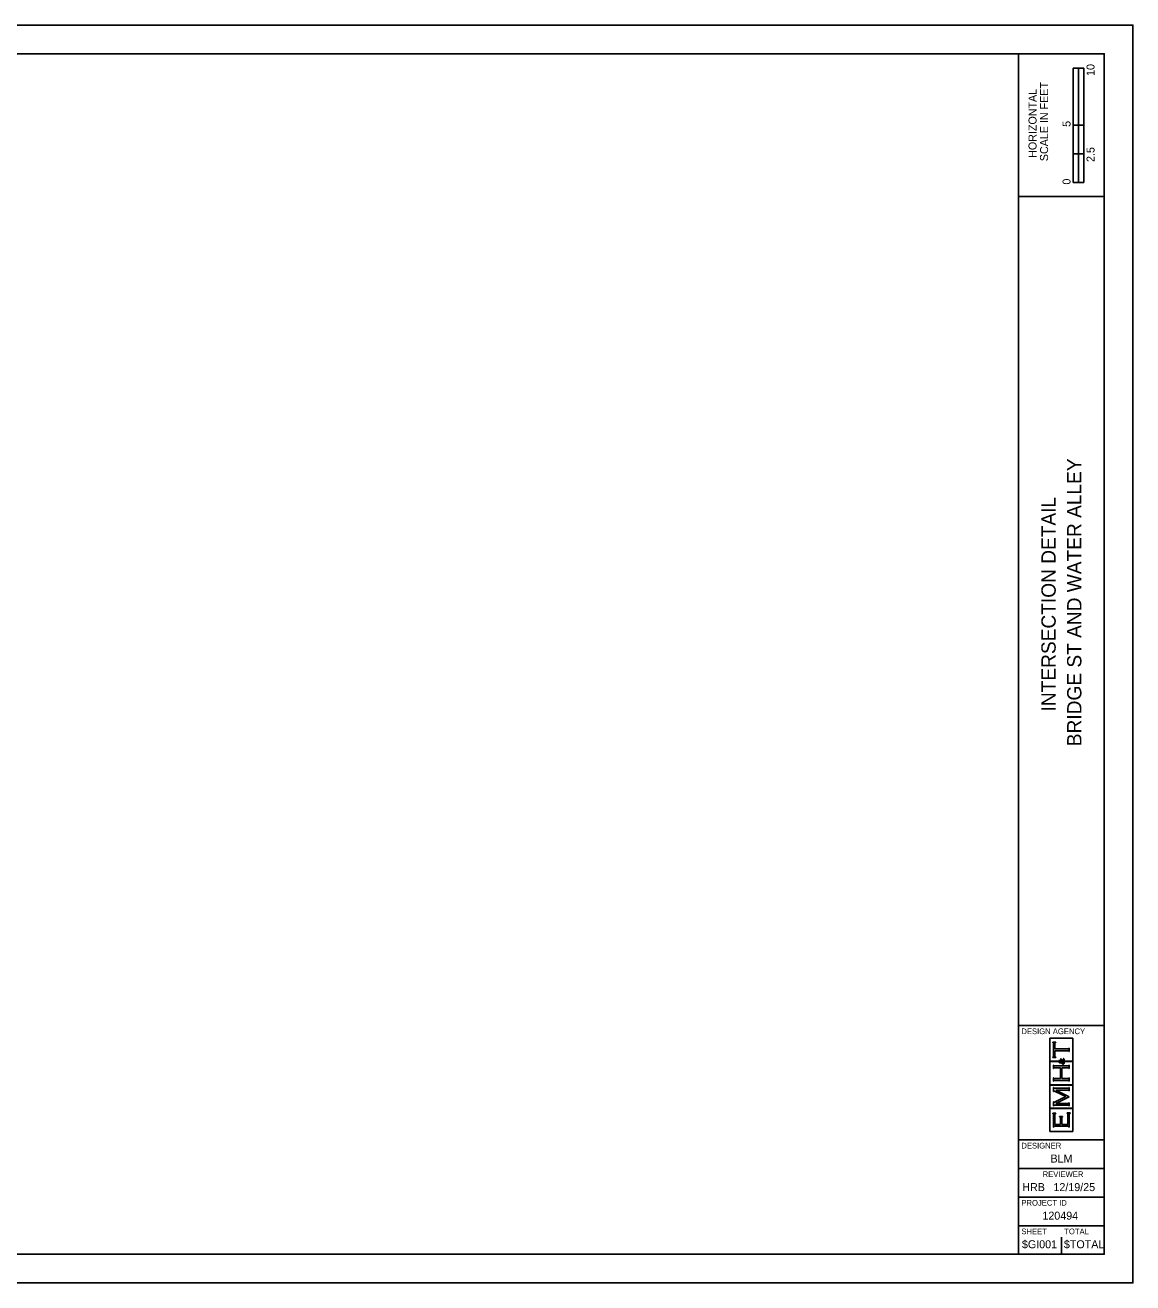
# Model space of a CAD drawing. Extents: x -4.8 to 34, y 0 to 22.
# Drawn here: x 14.62 to 34, y 0 to 22 of the extents above; entities that cross this region are included whole.
import ezdxf

# ---------------------------------------------------------------- set-up
doc = ezdxf.new("R2010")
doc.units = 0
for name, color, linetype in [('CM_Corridor_Conceptual', 7, 'Continuous'), ('CM_Corridor_Range_Conceptual', 7, 'Continuous'), ('MD_P_ACB_B', 7, 'Continuous')]:
    doc.layers.add(name, color=color, linetype=linetype)

msp = doc.modelspace()

# ---------------------------------------------------------------- linework, layer by layer
at = {"layer": 'CM_Corridor_Conceptual'}
msp.add_lwpolyline([(0, 0), (34, 0), (34, 22), (0, 22)], close=True, dxfattribs=at)
at = {"layer": 'CM_Corridor_Range_Conceptual'}
for p, q in [((32, 0.5), (32, 21.5)), ((32, 19), (33.5, 19)), ((32, 4.5), (33.5, 4.5)), ((32, 2.5), (33.5, 2.5)), ((32, 2), (33.5, 2)), ((32, 1.5), (33.5, 1.5)), ((32, 1), (33.5, 1))]:
    msp.add_line(p, q, dxfattribs=at)
msp.add_lwpolyline([(1.5, 21.5), (33.5, 21.5), (33.5, 0.5), (1.5, 0.5)], close=True, dxfattribs=at)
at = {"layer": 'MD_P_ACB_B'}
for p, q in [((32.957, 19.25), (32.957, 21.25)), ((33.144, 21.25), (32.957, 21.25)), ((32.957, 20.25), (32.957, 21.25)), ((32.957, 21.25), (33.05, 21.25)), ((33.05, 21.25), (33.051, 21.25)), ((33.051, 21.25), (33.051, 20.25)), ((33.144, 21.25), (33.144, 19.25)), ((33.051, 20.25), (32.957, 20.25)), ((33.143, 20.25), (33.05, 20.25)), ((33.05, 20.25), (33.05, 19.75)), ((33.143, 19.75), (33.143, 20.25)), ((33.05, 19.75), (32.957, 19.75)), ((32.957, 19.75), (32.957, 19.25)), ((33.05, 19.25), (33.05, 19.75)), ((33.05, 19.75), (33.143, 19.75)), ((33.144, 19.25), (32.957, 19.25)), ((32.957, 19.25), (33.05, 19.25)), ((32.952, 4.279), (32.547, 4.279)), ((32.547, 4.279), (32.547, 3.875)), ((32.598, 4.204), (32.598, 4.211)), ((32.598, 4.211), (32.65, 4.211)), ((32.603, 4.203), (32.598, 4.204)), ((32.606, 4.201), (32.603, 4.203)), ((32.608, 4.199), (32.606, 4.201)), ((32.61, 4.196), (32.608, 4.199)), ((32.611, 4.192), (32.61, 4.196)), ((32.611, 4.187), (32.611, 4.192)), ((32.611, 3.968), (32.611, 4.187)), ((32.638, 4.196), (32.637, 4.192)), ((32.637, 4.192), (32.637, 4.187)), ((32.637, 4.187), (32.637, 4.093)), ((32.64, 4.199), (32.638, 4.196)), ((32.642, 4.201), (32.64, 4.199)), ((32.645, 4.203), (32.642, 4.201)), ((32.65, 4.204), (32.645, 4.203)), ((32.65, 4.211), (32.65, 4.204)), ((32.952, 3.875), (32.952, 4.279)), ((32.61, 3.958), (32.611, 3.962)), ((32.611, 3.962), (32.611, 3.968)), ((32.637, 4.093), (32.864, 4.093)), ((32.864, 4.061), (32.637, 4.061)), ((32.637, 4.061), (32.637, 3.968)), ((32.637, 3.968), (32.637, 3.962)), ((32.637, 3.962), (32.638, 3.958)), ((32.864, 4.093), (32.869, 4.093)), ((32.87, 4.061), (32.864, 4.061)), ((32.869, 4.093), (32.873, 4.094)), ((32.874, 4.06), (32.87, 4.061)), ((32.873, 4.094), (32.876, 4.096)), ((32.876, 4.059), (32.874, 4.06)), ((32.876, 4.096), (32.878, 4.097)), ((32.878, 4.057), (32.876, 4.059)), ((32.878, 4.097), (32.88, 4.101)), ((32.88, 4.053), (32.878, 4.057)), ((32.88, 4.101), (32.881, 4.106)), ((32.881, 4.048), (32.88, 4.053)), ((32.881, 4.106), (32.888, 4.106)), ((32.888, 4.048), (32.881, 4.048)), ((32.888, 4.106), (32.888, 4.048)), ((32.547, 3.875), (32.696, 3.875)), ((32.696, 3.869), (32.547, 3.869)), ((32.547, 3.869), (32.547, 3.465)), ((32.598, 3.95), (32.603, 3.951)), ((32.598, 3.944), (32.598, 3.95)), ((32.65, 3.944), (32.598, 3.944)), ((32.603, 3.951), (32.606, 3.953)), ((32.606, 3.953), (32.608, 3.955)), ((32.608, 3.955), (32.61, 3.958)), ((32.611, 3.749), (32.611, 3.807)), ((32.611, 3.807), (32.617, 3.807)), ((32.617, 3.749), (32.611, 3.749)), ((32.617, 3.807), (32.619, 3.802)), ((32.618, 3.754), (32.617, 3.749)), ((32.62, 3.758), (32.618, 3.754)), ((32.619, 3.802), (32.62, 3.798)), ((32.62, 3.798), (32.623, 3.797)), ((32.623, 3.76), (32.62, 3.758)), ((32.623, 3.797), (32.625, 3.795)), ((32.625, 3.761), (32.623, 3.76)), ((32.625, 3.795), (32.629, 3.794)), ((32.629, 3.762), (32.625, 3.761)), ((32.629, 3.794), (32.635, 3.794)), ((32.635, 3.762), (32.629, 3.762)), ((32.635, 3.794), (32.864, 3.794)), ((32.732, 3.762), (32.635, 3.762)), ((32.638, 3.958), (32.64, 3.955)), ((32.64, 3.955), (32.642, 3.953)), ((32.642, 3.953), (32.645, 3.951)), ((32.645, 3.951), (32.65, 3.95)), ((32.65, 3.95), (32.65, 3.944)), ((32.696, 3.875), (32.696, 3.869)), ((32.703, 3.879), (32.705, 3.883)), ((32.703, 3.873), (32.703, 3.879)), ((32.703, 3.868), (32.703, 3.873)), ((32.705, 3.863), (32.703, 3.868)), ((32.705, 3.883), (32.708, 3.887)), ((32.708, 3.858), (32.705, 3.863)), ((32.708, 3.887), (32.711, 3.89)), ((32.709, 3.879), (32.708, 3.876)), ((32.708, 3.876), (32.708, 3.873)), ((32.708, 3.873), (32.708, 3.869)), ((32.708, 3.869), (32.71, 3.866)), ((32.712, 3.853), (32.708, 3.858)), ((32.712, 3.881), (32.709, 3.879)), ((32.71, 3.866), (32.712, 3.864)), ((32.711, 3.89), (32.715, 3.892)), ((32.714, 3.883), (32.712, 3.881)), ((32.712, 3.864), (32.715, 3.862)), ((32.718, 3.85), (32.712, 3.853)), ((32.716, 3.884), (32.714, 3.883)), ((32.715, 3.892), (32.72, 3.892)), ((32.715, 3.862), (32.718, 3.861)), ((32.72, 3.884), (32.716, 3.884)), ((32.718, 3.861), (32.721, 3.861)), ((32.726, 3.85), (32.718, 3.85)), ((32.72, 3.892), (32.725, 3.892)), ((32.724, 3.884), (32.72, 3.884)), ((32.721, 3.861), (32.723, 3.861)), ((32.723, 3.861), (32.725, 3.862)), ((32.728, 3.882), (32.724, 3.884)), ((32.725, 3.892), (32.729, 3.89)), ((32.725, 3.862), (32.728, 3.862)), ((32.729, 3.85), (32.726, 3.85)), ((32.731, 3.88), (32.728, 3.882)), ((32.728, 3.862), (32.731, 3.863)), ((32.729, 3.89), (32.732, 3.887)), ((32.731, 3.85), (32.729, 3.85)), ((32.734, 3.877), (32.731, 3.88)), ((32.731, 3.863), (32.735, 3.865)), ((32.734, 3.851), (32.731, 3.85)), ((32.732, 3.887), (32.736, 3.883)), ((32.732, 3.572), (32.732, 3.762)), ((32.737, 3.872), (32.734, 3.877)), ((32.737, 3.852), (32.734, 3.851)), ((32.735, 3.865), (32.74, 3.867)), ((32.736, 3.883), (32.74, 3.878)), ((32.74, 3.867), (32.737, 3.872)), ((32.741, 3.853), (32.737, 3.852)), ((32.738, 3.893), (32.738, 3.922)), ((32.738, 3.922), (32.741, 3.922)), ((32.741, 3.893), (32.738, 3.893)), ((32.74, 3.878), (32.744, 3.869)), ((32.741, 3.922), (32.741, 3.918)), ((32.741, 3.918), (32.742, 3.915)), ((32.742, 3.896), (32.741, 3.895)), ((32.741, 3.895), (32.741, 3.893)), ((32.746, 3.855), (32.741, 3.853)), ((32.742, 3.915), (32.743, 3.913)), ((32.743, 3.897), (32.742, 3.896)), ((32.743, 3.913), (32.745, 3.911)), ((32.745, 3.899), (32.743, 3.897)), ((32.744, 3.869), (32.754, 3.875)), ((32.745, 3.911), (32.749, 3.908)), ((32.746, 3.899), (32.745, 3.899)), ((32.748, 3.899), (32.746, 3.899)), ((32.752, 3.844), (32.746, 3.855)), ((32.755, 3.899), (32.748, 3.899)), ((32.749, 3.908), (32.756, 3.904)), ((32.756, 3.86), (32.751, 3.857)), ((32.751, 3.857), (32.754, 3.852)), ((32.757, 3.837), (32.752, 3.844)), ((32.754, 3.875), (32.764, 3.881)), ((32.754, 3.852), (32.757, 3.848)), ((32.763, 3.895), (32.755, 3.899)), ((32.756, 3.904), (32.763, 3.9)), ((32.761, 3.863), (32.756, 3.86)), ((32.757, 3.848), (32.761, 3.845)), ((32.763, 3.833), (32.757, 3.837)), ((32.864, 3.762), (32.759, 3.762)), ((32.759, 3.762), (32.759, 3.572)), ((32.764, 3.865), (32.761, 3.863)), ((32.761, 3.845), (32.765, 3.843)), ((32.763, 3.9), (32.77, 3.896)), ((32.772, 3.887), (32.763, 3.895)), ((32.768, 3.829), (32.763, 3.833)), ((32.764, 3.881), (32.772, 3.887)), ((32.768, 3.867), (32.764, 3.865)), ((32.765, 3.843), (32.769, 3.841)), ((32.774, 3.872), (32.768, 3.867)), ((32.774, 3.827), (32.768, 3.829)), ((32.769, 3.841), (32.773, 3.841)), ((32.77, 3.896), (32.776, 3.891)), ((32.773, 3.841), (32.778, 3.841)), ((32.782, 3.878), (32.774, 3.872)), ((32.779, 3.827), (32.774, 3.827)), ((32.776, 3.891), (32.781, 3.895)), ((32.778, 3.841), (32.782, 3.843)), ((32.779, 3.923), (32.781, 3.926)), ((32.782, 3.922), (32.779, 3.923)), ((32.785, 3.827), (32.779, 3.827)), ((32.781, 3.926), (32.787, 3.924)), ((32.781, 3.895), (32.784, 3.898)), ((32.785, 3.921), (32.782, 3.922)), ((32.786, 3.873), (32.782, 3.878)), ((32.782, 3.843), (32.786, 3.846)), ((32.784, 3.898), (32.786, 3.901)), ((32.786, 3.919), (32.785, 3.921)), ((32.79, 3.829), (32.785, 3.827)), ((32.788, 3.917), (32.786, 3.919)), ((32.786, 3.901), (32.788, 3.904)), ((32.791, 3.886), (32.786, 3.881)), ((32.786, 3.881), (32.791, 3.876)), ((32.788, 3.869), (32.786, 3.873)), ((32.786, 3.846), (32.789, 3.849)), ((32.787, 3.924), (32.792, 3.921)), ((32.789, 3.914), (32.788, 3.917)), ((32.788, 3.904), (32.789, 3.908)), ((32.79, 3.867), (32.788, 3.869)), ((32.789, 3.911), (32.789, 3.914)), ((32.789, 3.908), (32.789, 3.911)), ((32.789, 3.849), (32.791, 3.853)), ((32.791, 3.864), (32.79, 3.867)), ((32.793, 3.834), (32.79, 3.829)), ((32.794, 3.89), (32.791, 3.886)), ((32.791, 3.876), (32.795, 3.87)), ((32.791, 3.861), (32.791, 3.864)), ((32.791, 3.859), (32.791, 3.861)), ((32.791, 3.853), (32.791, 3.859)), ((32.792, 3.921), (32.795, 3.918)), ((32.797, 3.838), (32.793, 3.834)), ((32.796, 3.894), (32.794, 3.89)), ((32.795, 3.918), (32.798, 3.914)), ((32.795, 3.87), (32.797, 3.866)), ((32.798, 3.897), (32.796, 3.894)), ((32.797, 3.866), (32.798, 3.861)), ((32.799, 3.844), (32.797, 3.838)), ((32.798, 3.914), (32.799, 3.91)), ((32.799, 3.901), (32.798, 3.897)), ((32.798, 3.861), (32.799, 3.857)), ((32.799, 3.91), (32.799, 3.905)), ((32.799, 3.905), (32.799, 3.901)), ((32.803, 3.869), (32.799, 3.875)), ((32.799, 3.875), (32.952, 3.875)), ((32.799, 3.857), (32.799, 3.852)), ((32.799, 3.852), (32.799, 3.844)), ((32.952, 3.869), (32.803, 3.869)), ((32.864, 3.794), (32.869, 3.794)), ((32.87, 3.762), (32.864, 3.762)), ((32.869, 3.794), (32.873, 3.795)), ((32.874, 3.761), (32.87, 3.762)), ((32.873, 3.795), (32.876, 3.797)), ((32.876, 3.76), (32.874, 3.761)), ((32.876, 3.797), (32.878, 3.798)), ((32.878, 3.758), (32.876, 3.76)), ((32.878, 3.798), (32.88, 3.802)), ((32.88, 3.754), (32.878, 3.758)), ((32.88, 3.802), (32.881, 3.807)), ((32.881, 3.749), (32.88, 3.754)), ((32.881, 3.807), (32.888, 3.807)), ((32.888, 3.749), (32.881, 3.749)), ((32.888, 3.807), (32.888, 3.749)), ((32.952, 3.465), (32.952, 3.869)), ((32.611, 3.527), (32.611, 3.585)), ((32.611, 3.585), (32.617, 3.585)), ((32.617, 3.527), (32.611, 3.527)), ((32.617, 3.585), (32.619, 3.58)), ((32.618, 3.532), (32.617, 3.527)), ((32.62, 3.536), (32.618, 3.532)), ((32.619, 3.58), (32.62, 3.576)), ((32.62, 3.576), (32.623, 3.574)), ((32.623, 3.537), (32.62, 3.536)), ((32.623, 3.574), (32.625, 3.573)), ((32.625, 3.539), (32.623, 3.537)), ((32.625, 3.573), (32.629, 3.572)), ((32.629, 3.54), (32.625, 3.539)), ((32.629, 3.572), (32.635, 3.572)), ((32.635, 3.54), (32.629, 3.54)), ((32.635, 3.572), (32.732, 3.572)), ((32.864, 3.54), (32.635, 3.54)), ((32.759, 3.572), (32.864, 3.572)), ((32.864, 3.572), (32.87, 3.572)), ((32.87, 3.54), (32.864, 3.54)), ((32.87, 3.572), (32.874, 3.573)), ((32.874, 3.539), (32.87, 3.54)), ((32.874, 3.573), (32.876, 3.574)), ((32.876, 3.538), (32.874, 3.539)), ((32.876, 3.574), (32.878, 3.576)), ((32.878, 3.536), (32.876, 3.538)), ((32.878, 3.576), (32.88, 3.58)), ((32.88, 3.532), (32.878, 3.536)), ((32.88, 3.58), (32.881, 3.585)), ((32.881, 3.527), (32.88, 3.532)), ((32.881, 3.585), (32.888, 3.585)), ((32.888, 3.527), (32.881, 3.527)), ((32.888, 3.585), (32.888, 3.527)), ((32.547, 3.465), (32.952, 3.465)), ((32.952, 3.459), (32.547, 3.459)), ((32.547, 3.459), (32.547, 3.055)), ((32.611, 3.345), (32.611, 3.418)), ((32.611, 3.418), (32.617, 3.418)), ((32.617, 3.345), (32.611, 3.345)), ((32.617, 3.418), (32.619, 3.412)), ((32.62, 3.352), (32.617, 3.345)), ((32.619, 3.412), (32.62, 3.409)), ((32.62, 3.409), (32.623, 3.407)), ((32.622, 3.355), (32.62, 3.352)), ((32.626, 3.355), (32.622, 3.355)), ((32.623, 3.407), (32.625, 3.405)), ((32.625, 3.405), (32.629, 3.405)), ((32.629, 3.355), (32.626, 3.355)), ((32.629, 3.405), (32.635, 3.405)), ((32.633, 3.353), (32.629, 3.355)), ((32.64, 3.35), (32.633, 3.353)), ((32.635, 3.405), (32.864, 3.405)), ((32.825, 3.257), (32.64, 3.35)), ((32.864, 3.373), (32.654, 3.373)), ((32.654, 3.373), (32.888, 3.255)), ((32.75, 3.5), (32.75, 3.5)), ((32.864, 3.405), (32.869, 3.405)), ((32.87, 3.373), (32.864, 3.373)), ((32.869, 3.405), (32.873, 3.405)), ((32.874, 3.372), (32.87, 3.373)), ((32.873, 3.405), (32.876, 3.407)), ((32.876, 3.37), (32.874, 3.372)), ((32.876, 3.407), (32.878, 3.409)), ((32.878, 3.369), (32.876, 3.37)), ((32.878, 3.409), (32.88, 3.412)), ((32.88, 3.365), (32.878, 3.369)), ((32.88, 3.412), (32.881, 3.418)), ((32.881, 3.36), (32.88, 3.365)), ((32.881, 3.418), (32.888, 3.418)), ((32.888, 3.36), (32.881, 3.36)), ((32.888, 3.418), (32.888, 3.36)), ((32.952, 3.055), (32.952, 3.459)), ((32.611, 3.096), (32.611, 3.168)), ((32.611, 3.168), (32.617, 3.168)), ((32.617, 3.096), (32.611, 3.096)), ((32.617, 3.168), (32.62, 3.162)), ((32.618, 3.102), (32.617, 3.096)), ((32.62, 3.105), (32.618, 3.102)), ((32.62, 3.162), (32.622, 3.158)), ((32.623, 3.107), (32.62, 3.105)), ((32.622, 3.158), (32.626, 3.158)), ((32.625, 3.109), (32.623, 3.107)), ((32.629, 3.109), (32.625, 3.109)), ((32.626, 3.158), (32.627, 3.158)), ((32.627, 3.158), (32.633, 3.161)), ((32.635, 3.109), (32.629, 3.109)), ((32.633, 3.161), (32.641, 3.165)), ((32.864, 3.109), (32.635, 3.109)), ((32.641, 3.165), (32.825, 3.257)), ((32.888, 3.255), (32.654, 3.138)), ((32.654, 3.138), (32.864, 3.138)), ((32.864, 3.138), (32.869, 3.138)), ((32.87, 3.109), (32.864, 3.109)), ((32.869, 3.138), (32.873, 3.139)), ((32.874, 3.109), (32.87, 3.109)), ((32.873, 3.139), (32.876, 3.141)), ((32.876, 3.107), (32.874, 3.109)), ((32.876, 3.141), (32.878, 3.143)), ((32.878, 3.105), (32.876, 3.107)), ((32.878, 3.143), (32.88, 3.146)), ((32.88, 3.102), (32.878, 3.105)), ((32.88, 3.146), (32.881, 3.151)), ((32.881, 3.096), (32.88, 3.102)), ((32.881, 3.151), (32.888, 3.151)), ((32.888, 3.096), (32.881, 3.096)), ((32.888, 3.151), (32.888, 3.096)), ((32.547, 3.055), (32.952, 3.055)), ((32.952, 3.049), (32.547, 3.049)), ((32.547, 3.049), (32.547, 2.645)), ((32.598, 2.962), (32.598, 2.969)), ((32.598, 2.969), (32.65, 2.969)), ((32.603, 2.961), (32.598, 2.962)), ((32.606, 2.959), (32.603, 2.961)), ((32.608, 2.957), (32.606, 2.959)), ((32.61, 2.955), (32.608, 2.957)), ((32.611, 2.951), (32.61, 2.955)), ((32.611, 2.945), (32.611, 2.951)), ((32.611, 2.725), (32.611, 2.945)), ((32.64, 2.957), (32.638, 2.955)), ((32.638, 2.955), (32.638, 2.951)), ((32.638, 2.951), (32.638, 2.945)), ((32.638, 2.945), (32.638, 2.77)), ((32.642, 2.959), (32.64, 2.957)), ((32.645, 2.961), (32.642, 2.959)), ((32.65, 2.962), (32.645, 2.961)), ((32.65, 2.969), (32.65, 2.962)), ((32.719, 2.902), (32.719, 2.908)), ((32.719, 2.908), (32.772, 2.908)), ((32.724, 2.901), (32.719, 2.902)), ((32.728, 2.899), (32.724, 2.901)), ((32.729, 2.896), (32.728, 2.899)), ((32.731, 2.894), (32.729, 2.896)), ((32.732, 2.89), (32.731, 2.894)), ((32.732, 2.884), (32.732, 2.89)), ((32.732, 2.77), (32.732, 2.884)), ((32.76, 2.894), (32.759, 2.89)), ((32.759, 2.89), (32.759, 2.884)), ((32.759, 2.884), (32.759, 2.77)), ((32.761, 2.896), (32.76, 2.894)), ((32.763, 2.899), (32.761, 2.896)), ((32.767, 2.901), (32.763, 2.899)), ((32.772, 2.902), (32.767, 2.901)), ((32.772, 2.908), (32.772, 2.902)), ((32.848, 2.965), (32.848, 2.972)), ((32.848, 2.972), (32.901, 2.972)), ((32.853, 2.964), (32.848, 2.965)), ((32.857, 2.962), (32.853, 2.964)), ((32.859, 2.96), (32.857, 2.962)), ((32.86, 2.958), (32.859, 2.96)), ((32.861, 2.953), (32.86, 2.958)), ((32.861, 2.948), (32.861, 2.953)), ((32.861, 2.77), (32.861, 2.948)), ((32.889, 2.957), (32.888, 2.953)), ((32.888, 2.953), (32.888, 2.948)), ((32.888, 2.948), (32.888, 2.725)), ((32.891, 2.96), (32.889, 2.957)), ((32.892, 2.962), (32.891, 2.96)), ((32.896, 2.964), (32.892, 2.962)), ((32.901, 2.965), (32.896, 2.964)), ((32.901, 2.972), (32.901, 2.965)), ((32.952, 2.645), (32.952, 3.049)), ((32.547, 2.645), (32.952, 2.645)), ((32.617, 2.725), (32.611, 2.725)), ((32.619, 2.73), (32.617, 2.725)), ((32.62, 2.734), (32.619, 2.73)), ((32.623, 2.735), (32.62, 2.734)), ((32.625, 2.737), (32.623, 2.735)), ((32.629, 2.738), (32.625, 2.737)), ((32.635, 2.738), (32.629, 2.738)), ((32.864, 2.738), (32.635, 2.738)), ((32.638, 2.77), (32.732, 2.77)), ((32.759, 2.77), (32.861, 2.77)), ((32.87, 2.738), (32.864, 2.738)), ((32.874, 2.737), (32.87, 2.738)), ((32.876, 2.735), (32.874, 2.737)), ((32.878, 2.734), (32.876, 2.735)), ((32.88, 2.73), (32.878, 2.734)), ((32.881, 2.725), (32.88, 2.73)), ((32.888, 2.725), (32.881, 2.725)), ((32.375, 0.675), (32.375, 0.675)), ((32.75, 0.5), (32.75, 0.8))]:
    msp.add_line(p, q, dxfattribs=at)

# ---------------------------------------------------------------- texts
for s, height, p in [('10', 0.14, (33.33, 21.112)), ('SCALE IN FEET', 0.14, (32.517, 19.621)), ('HORIZONTAL', 0.14, (32.315, 19.679)), ('5', 0.14, (32.91, 20.221)), ('2.5', 0.14, (33.33, 19.607)), ('0', 0.14, (32.91, 19.211)), ('BRIDGE ST AND WATER ALLEY', 0.25, (33.1, 9.387)), ('INTERSECTION DETAIL', 0.25, (32.65, 9.996))]:
    msp.add_text(s, height=height, rotation=90, dxfattribs=at).set_placement(p)
for s, height, p in [('DESIGN AGENCY', 0.1, (32.05, 4.35)), ('DESIGNER', 0.1, (32.05, 2.35)), ('BLM', 0.14, (32.559, 2.105)), ('REVIEWER', 0.1, (32.422, 1.85)), ('HRB', 0.14, (32.066, 1.605)), ('12/19/25', 0.14, (32.611, 1.605)), ('PROJECT ID', 0.1, (32.05, 1.35)), ('120494', 0.14, (32.418, 1.105)), ('SHEET', 0.1, (32.05, 0.85)), ('TOTAL', 0.1, (32.8, 0.85)), ('$GI001', 0.14, (32.06, 0.605)), ('$TOTAL', 0.14, (32.794, 0.605))]:
    msp.add_text(s, height=height, dxfattribs=at).set_placement(p)

doc.saveas('drawing.dxf')
